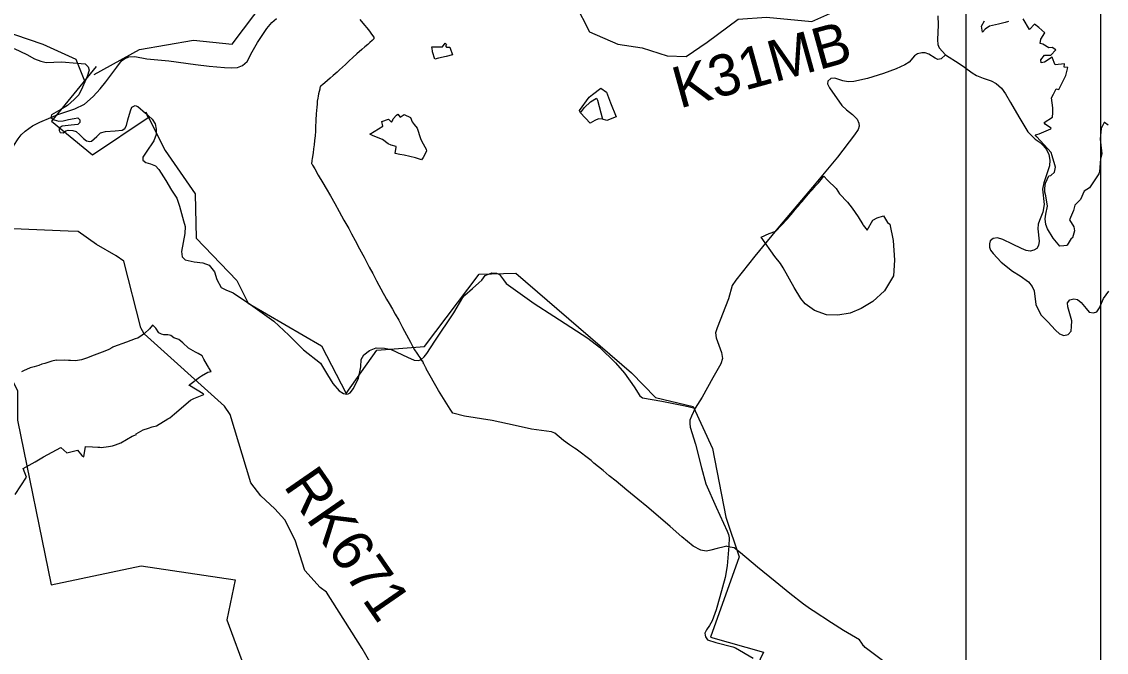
# Model space of a CAD drawing. Extents: x -789162 to -606354, y -1062736 to -945481.
# Drawn here: x -677802 to -673868, y -992822 to -990534 of the extents above; entities that cross this region are included whole.
import ezdxf

# ---------------------------------------------------------------- set-up
doc = ezdxf.new("R2010")
doc.units = 0
for name, color, linetype in [('_Rámeček', 7, 'Continuous'), ('_SIRSI VZTAHY_CYKLOTRASY MISTNI S', 7, 'Continuous'), ('_SIRSI VZTAHY_OP vodnich zdroju II stupne', 7, 'Continuous'), ('_SIRSI VZTAHY_SILNICE II TRIDY_STAV', 7, 'Continuous'), ('_SIRSI VZTAHY_SILNICE III TRIDY_STAV', 7, 'Continuous'), ('_SIRSI VZTAHY_USES_NRBC_S', 7, 'Continuous'), ('_SIRSI VZTAHY_USES_NRBK_S', 7, 'Continuous'), ('_SIRSI VZTAHY_USES_popis S', 7, 'Continuous'), ('_SIRSI VZTAHY_USES_RBK_S', 7, 'Continuous'), ('_SIRSI VZTAHY_VTL PLYNOVOD', 7, 'Continuous')]:
    doc.layers.add(name, color=color, linetype=linetype)

msp = doc.modelspace()

# ---------------------------------------------------------------- linework, layer by layer
at = {"layer": '_Rámeček'}
msp.add_lwpolyline([(-673887.2, -995977.3), (-673887.2, -966277.3), (-694887.2, -966277.3), (-694887.2, -995977.3)], close=True, dxfattribs=at)
msp.add_lwpolyline([(-674375.7, -995477.3), (-674375.7, -975976.1), (-694376.9, -975976.1), (-694376.9, -995477.3)], dxfattribs=at)
at = {"layer": '_SIRSI VZTAHY_CYKLOTRASY MISTNI S'}
for points in [[(-677538.3, -990724.9), (-677374.1, -990635), (-677178.3, -990600.9), (-677038.1, -990614.6), (-676918.4, -990457.2), (-676720, -990323.8), (-676593.5, -990299.8), (-676644.8, -990108.2), (-676566.2, -989978.1), (-676183.1, -989991.8), (-675933.5, -989844.7), (-675670.2, -989875.5), (-675396.6, -989998.7), (-675502.6, -989813.9), (-675834.3, -989697.5), (-675957.4, -989492.2)], [(-677573.3, -990749.2), (-677604, -990670.5), (-677724.4, -990616.5), (-678033.5, -990511.6)], [(-678766.8, -990700.2), (-678671.7, -990917.3), (-678371.7, -991161.7), (-678252.2, -991206.9), (-678082, -991285.8), (-678105.9, -991437.2), (-678023.6, -991453.2), (-677816.4, -991873), (-677816.4, -991979.3), (-677694.3, -992577.1), (-677369, -992507.8), (-677027.1, -992559.1), (-677057.4, -992704.3), (-676986, -992897.9), (-676961.7, -993127.6), (-676799.6, -993327.7), (-676711.2, -993548.4)], [(-677531.2, -990696.4), (-677694, -990894), (-677545.3, -991016.3), (-677343.5, -990880.7), (-677351.4, -990862.1), (-677281.6, -991001), (-677172.2, -991158.4), (-677168.8, -991319.2), (-677021, -991473), (-676980, -991555.1), (-676713.9, -991709.3), (-676625.4, -991882.5), (-676513.9, -991725.7), (-676341.2, -991712.7), (-676142.2, -991449.4), (-676009.5, -991445.8), (-675589.9, -991808.1), (-675502.6, -991897.5), (-675366.8, -991930.3), (-675295.6, -992081.9), (-675247.4, -992331.3), (-675199.6, -992475), (-675303.1, -992767.3), (-675110.9, -992821), (-675170.4, -992945.3)]]:
    msp.add_lwpolyline(points, dxfattribs=at)
at = {"layer": '_SIRSI VZTAHY_OP vodnich zdroju II stupne'}
for points in [[(-676312.2, -990639.3), (-676314.2, -990624.3), (-676275.9, -990624.2), (-676265.4, -990611.3), (-676261, -990615.8), (-676264.3, -990621.1), (-676261.4, -990626.2), (-676248.6, -990626), (-676247.4, -990629.9), (-676239.5, -990654), (-676262.7, -990659.4), (-676289.6, -990666.2), (-676303.5, -990669.4), (-676311.7, -990643.4)], [(-675775.3, -990864.8), (-675778.9, -990855.5), (-675744, -990807.8), (-675732, -990797.9), (-675700.6, -990774.6), (-675681.1, -990789.1), (-675665.6, -990827.8), (-675645.1, -990878.3), (-675679.1, -990891.7), (-675694.7, -990887.7), (-675709.1, -990886.6), (-675723.4, -990891.8), (-675740, -990901.9)], [(-675694.7, -990887.7), (-675709.1, -990886.6), (-675723.4, -990891.8), (-675740, -990901.9), (-675775.3, -990864.8), (-675759.9, -990844.6), (-675738.4, -990824.7), (-675716.7, -990811.3), (-675713.1, -990818)], [(-676334.6, -990995.8), (-676333.2, -991003.5), (-676346.1, -991025.9), (-676351.9, -991034.9), (-676373.2, -991027.6), (-676414.1, -991018.1), (-676429.8, -991014.9), (-676447.4, -991012.1), (-676443.6, -990989.1), (-676443.7, -990985.9), (-676462.1, -990981.9), (-676472.7, -990976.9), (-676493.5, -990961.6), (-676527.2, -990947.6), (-676539.6, -990941.2), (-676492.2, -990912.6), (-676495.1, -990895.2), (-676471.5, -990886.7), (-676460.5, -990897.8), (-676457.4, -990893.1), (-676454.6, -990886), (-676442.4, -990872.9), (-676438, -990869), (-676429.1, -990879.4), (-676425.5, -990877.5), (-676414.8, -990870.2), (-676391.6, -990881.6), (-676385, -990897.4), (-676378, -990906.1), (-676367.5, -990920.4), (-676355.2, -990957), (-676350.4, -990968.4)], [(-674892.5, -991093.6), (-674878.9, -991108), (-674847.3, -991139.3), (-674835.7, -991157.7), (-674806.2, -991188.8), (-674789.6, -991210.6), (-674767.3, -991241.2), (-674750.5, -991269.7), (-674749.4, -991271.7), (-674735.2, -991290.5), (-674714.6, -991254), (-674699.5, -991244.7), (-674676, -991238.2), (-674661.1, -991261.9), (-674652.6, -991268.7), (-674640.8, -991327.7), (-674635.5, -991398.5), (-674639.5, -991456), (-674672.6, -991509.7), (-674714.3, -991549.4), (-674757.3, -991573.8), (-674796.9, -991590.9), (-674841.9, -991598.8), (-674882.2, -991597.5), (-674925.8, -991581.7), (-674959.5, -991557.3), (-674975.8, -991537.6), (-674999.8, -991498.6), (-675040.2, -991427.2), (-675049.2, -991411.2), (-675070.2, -991385.1), (-675120.2, -991315.1), (-675090.1, -991302.6), (-675066.8, -991293.4), (-675025.6, -991250.7), (-675005.2, -991225.9), (-675000.6, -991220.5), (-674988.8, -991206.2), (-674984.7, -991202), (-674977.8, -991193.8), (-674972.7, -991187.6), (-674965.5, -991178.4), (-674961.1, -991173.9), (-674952.9, -991164.4), (-674948.6, -991159.9), (-674939.1, -991148.7), (-674935.5, -991144.5), (-674926.5, -991133.5), (-674922.5, -991128.8), (-674912.1, -991117.7)]]:
    msp.add_lwpolyline(points, close=True, dxfattribs=at)
msp.add_lwpolyline([(-677825, -992249.1), (-677784.1, -992185.8), (-677796.3, -992154.4), (-677752.7, -992130.3), (-677723, -992112.8), (-677660.3, -992079), (-677638.6, -992098.2), (-677599.6, -992088.1), (-677583.6, -992107.4), (-677576.1, -992112.1), (-677570.6, -992075), (-677545.4, -992076.1), (-677525.2, -992077.5), (-677521.1, -992077.5), (-677518.7, -992077.5), (-677513.4, -992078.9), (-677486.8, -992075.4), (-677472.4, -992073), (-677461.6, -992069.2), (-677441.8, -992061.1), (-677421.6, -992050.2), (-677401.3, -992037.4), (-677385.7, -992031.4), (-677386.4, -992028.9), (-677361.5, -992014.5), (-677341.3, -992008.4), (-677328.1, -992004.1), (-677313.1, -991999.9), (-677271.4, -991975.2), (-677264.8, -991971.3), (-677247, -991956.2), (-677189.7, -991906.6), (-677177.9, -991900.8), (-677141.2, -991886.4), (-677143, -991884.1), (-677193.1, -991853.6), (-677195.3, -991853.4), (-677192, -991850.4), (-677156.3, -991823.1), (-677153.1, -991820.6), (-677149.7, -991818.8), (-677126.4, -991805.7), (-677114, -991802.7), (-677122.6, -991789.9), (-677124.2, -991787.4), (-677127.9, -991781.6), (-677140.9, -991757.6), (-677147.2, -991746.4), (-677161.1, -991738.1), (-677171.1, -991732.2), (-677197.2, -991718.5), (-677217.7, -991699.2), (-677231.8, -991687.3), (-677249.4, -991680.2), (-677260.9, -991672.7), (-677265.2, -991670.6), (-677271.7, -991669.3), (-677286.2, -991669.3), (-677295.2, -991667.2), (-677303.9, -991663), (-677315.4, -991645.3), (-677327.2, -991633.6), (-677327.7, -991634.4), (-677338.3, -991648.4), (-677356, -991664.5), (-677364.9, -991671), (-677380.6, -991682.4), (-677390.5, -991684.1), (-677421.9, -991695.9), (-677468.6, -991712.8), (-677471.6, -991714.6), (-677474.7, -991716.4), (-677485.8, -991722.9), (-677500.4, -991728.9), (-677538.9, -991743.8), (-677566.6, -991754.6), (-677585.3, -991760), (-677606.3, -991763.9), (-677624.8, -991762.9), (-677632.2, -991762.6), (-677646.9, -991762.1), (-677676.2, -991763.2), (-677676.4, -991762.1), (-677692.7, -991765), (-677718.4, -991773.3), (-677729, -991776.8), (-677739.5, -991781), (-677756.6, -991785.9), (-677770.6, -991790), (-677794.8, -991800.6), (-677794.9, -991800.7), (-677802.6, -991804)], dxfattribs=at)
at = {"layer": '_SIRSI VZTAHY_SILNICE II TRIDY_STAV'}
for points in [[(-674478.7, -990512.8), (-674477.8, -990545.1), (-674480.2, -990599.4), (-674479, -990615.9), (-674473.7, -990628.8), (-674450.8, -990653.8), (-674450.8, -990654.3)], [(-677695.9, -990880.7), (-677670.3, -990870.2), (-677641.4, -990860.8), (-677609.2, -990849.9), (-677573.9, -990832.5), (-677543.1, -990805.1), (-677517.4, -990777.6), (-677496.4, -990751.8), (-677456.1, -990698.3), (-677439.6, -990676), (-677428.3, -990667.9), (-677412.8, -990661.4), (-677391.4, -990659.6), (-677348.1, -990668.3), (-677268.6, -990675), (-677171.5, -990689.2), (-677121.2, -990695), (-677065.7, -990699.5), (-677042.1, -990700.8), (-677019.5, -990699.2), (-677000.5, -990692.8), (-676984.4, -990677.5), (-676965.6, -990643.3), (-676946, -990609.2), (-676912.4, -990557.9), (-676894.7, -990535.9), (-676877.3, -990522.1)], [(-674450.8, -990654.3), (-674401.4, -990684.8), (-674382, -990699.1), (-674353.8, -990718.9), (-674338.5, -990729), (-674314.4, -990738.8), (-674285.4, -990748.3), (-674267.3, -990757.3), (-674248.5, -990774.2), (-674234, -990795.4), (-674215.2, -990826.9), (-674184.6, -990878.9), (-674153, -990932.6), (-674125.8, -990959.9), (-674108, -990972.1), (-674096.9, -990982.2), (-674085.3, -990997.1), (-674076.8, -991015), (-674072.3, -991035.6), (-674073.4, -991057), (-674094.6, -991118.4), (-674098.7, -991141.1), (-674093.1, -991196.3), (-674098.5, -991224.7), (-674110.4, -991254.4), (-674114.9, -991267.7), (-674116.2, -991285.6), (-674111.7, -991330.1), (-674113.8, -991345.7), (-674119.7, -991356.3), (-674130.3, -991362.6), (-674144.3, -991365.8), (-674158.6, -991363.4), (-674175.8, -991356.8), (-674208.6, -991341.1), (-674243.5, -991324.4), (-674262.6, -991317.5), (-674278.8, -991320.5), (-674289.6, -991329.3), (-674291.4, -991339.2), (-674291.1, -991351.5), (-674288.2, -991362.4), (-674278.2, -991374.3), (-674248.8, -991406), (-674208.6, -991438.4), (-674180.6, -991456.1), (-674150.4, -991477.7), (-674136.3, -991494.1), (-674129.5, -991510.1), (-674123.5, -991560.2), (-674112.7, -991583), (-674103.8, -991598.6), (-674079.5, -991622.2), (-674052.2, -991652.9), (-674038.2, -991666.4), (-674022.4, -991671.8), (-674006.3, -991668.5), (-673995.7, -991656.3), (-673993.5, -991639.6), (-673992.3, -991618.8), (-674007.8, -991568.7), (-674008.3, -991554.2), (-673999.6, -991543.1), (-673986.1, -991539.3), (-673972.8, -991541), (-673959.6, -991552.8), (-673940.3, -991574.5), (-673930.2, -991587), (-673914.2, -991590.4), (-673902.6, -991586.1), (-673892.1, -991571.8), (-673878.4, -991538.2), (-673858.8, -991511.7)], [(-678065.8, -991300.3), (-678040.2, -991270.2), (-677995, -991235.4), (-677961, -991206.7), (-677919.4, -991166.7), (-677895.8, -991133), (-677877.8, -991092.8), (-677847.5, -991021.9), (-677830.2, -990982.9), (-677814.9, -990958.6), (-677804.2, -990943.8), (-677789.1, -990930.2), (-677762.3, -990911.8), (-677735.5, -990898.3), (-677695.9, -990880.7)]]:
    msp.add_lwpolyline(points, dxfattribs=at)
at = {"layer": '_SIRSI VZTAHY_SILNICE III TRIDY_STAV'}
for points in [[(-677829.3, -990631), (-677783, -990652.5), (-677755.1, -990668.8), (-677732, -990677.1), (-677713.1, -990681.3), (-677657.5, -990679.7), (-677601.1, -990684.1), (-677571.1, -990686.4), (-677560.4, -990697), (-677557.3, -990709.1), (-677564.3, -990732.9), (-677581.1, -990770.7), (-677594.4, -990799.2), (-677611.6, -990816.4), (-677635.7, -990837.3), (-677660.1, -990852.6), (-677693.5, -990871.3), (-677695.9, -990880.7)], [(-674450.8, -990654.3), (-674466.7, -990668.3), (-674478.7, -990670.9), (-674488.9, -990665.8), (-674511.4, -990651.2), (-674525.2, -990647.1), (-674537.5, -990647.1), (-674552.7, -990650.6), (-674563.5, -990657.5), (-674583.2, -990680.4), (-674598.1, -990690.2), (-674630.6, -990705), (-674676, -990722), (-674733.7, -990739.8), (-674783.5, -990750.9), (-674803.8, -990752.2), (-674822.9, -990748), (-674852.7, -990737.9), (-674866.4, -990739.8), (-674877.5, -990749), (-674879.5, -990758.7), (-674872.4, -990773.4), (-674826.6, -990837.5), (-674810.3, -990853.8), (-674787.9, -990870.4), (-674771.5, -990887), (-674765.4, -990902.3), (-674764.8, -990912.2), (-674768.3, -990924.9), (-674781, -990944.6), (-674842.9, -991025.5), (-674933.2, -991133.7), (-675053.2, -991276.1), (-675142.8, -991384.6), (-675211.8, -991471), (-675224.5, -991490.7), (-675238.5, -991538.6), (-675279.3, -991644), (-675284.9, -991662.8), (-675282.9, -991681.2), (-675263.3, -991734.4), (-675260.2, -991756.1), (-675265.9, -991774.7), (-675294.7, -991825.7), (-675334.1, -991896.1), (-675359.3, -991935.8)], [(-677695.9, -990880.7), (-677683.4, -990889.7), (-677666.7, -990894.7), (-677651.7, -990893.5), (-677631.7, -990888.8), (-677611.9, -990884.4), (-677598.2, -990882.4), (-677590.6, -990889.1), (-677590.6, -990899.6), (-677597.7, -990906), (-677621.7, -990909), (-677654.7, -990912.6), (-677665.5, -990920.2), (-677665.9, -990928.1), (-677662, -990935.1), (-677651.8, -990937.2), (-677641.1, -990929.1), (-677632.8, -990927.1), (-677616, -990928.8), (-677604.4, -990932.4), (-677590.8, -990944.1), (-677577.9, -990956.8), (-677566.9, -990965.8), (-677554.3, -990968.3), (-677548.7, -990966.8), (-677529.7, -990949.9), (-677515.3, -990937.4), (-677498.3, -990931.7), (-677463, -990929.1), (-677437.9, -990927.5), (-677427.4, -990920.8), (-677421.4, -990909.7), (-677416.6, -990890), (-677407, -990856.5), (-677401.7, -990843.9), (-677389.8, -990837.7), (-677380, -990841.4), (-677352.4, -990866), (-677328.9, -990887.3), (-677318, -990903.6), (-677313.7, -990923.4), (-677314.4, -990942.4), (-677322.6, -990965.3), (-677350.3, -991006.6), (-677362.3, -991025.6), (-677362, -991036.4), (-677351.6, -991044.3), (-677334, -991049), (-677316.6, -991056.4), (-677304.1, -991069.7), (-677279.1, -991110.1), (-677258.1, -991145.1), (-677239.3, -991173.7), (-677229.2, -991202.9), (-677214.4, -991256.1), (-677208.7, -991276.7), (-677209.9, -991302.5), (-677222.6, -991367.9), (-677220.1, -991386.9), (-677208.5, -991397.6), (-677176.4, -991405.1), (-677144.5, -991408), (-677121.2, -991416.9), (-677102.6, -991440.6), (-677094.2, -991468.7), (-677077.9, -991498), (-677060.8, -991506.6), (-677035.1, -991517.7), (-676971.9, -991559.8), (-676886.7, -991620.3), (-676833, -991670.9), (-676779.3, -991724.6), (-676717.8, -991772.6), (-676692.5, -991815), (-676673.4, -991846), (-676650.1, -991872.8), (-676634.7, -991883.2), (-676623.9, -991885.5), (-676617.9, -991884), (-676610.5, -991880), (-676598, -991864.2), (-676580.4, -991827), (-676572.2, -991786.2), (-676570, -991759.8), (-676560.4, -991742.9), (-676540.7, -991727.2), (-676516.3, -991717.5), (-676485.6, -991718), (-676462.2, -991722.5), (-676402.7, -991750.9), (-676377.8, -991761.3), (-676360.9, -991762.9), (-676352.3, -991759.7), (-676341.7, -991750), (-676332.4, -991737.9), (-676303.1, -991692.4), (-676234.6, -991589.8), (-676201.2, -991534.1), (-676194.6, -991525.6), (-676166.1, -991502), (-676143.6, -991481.1), (-676133.1, -991471.4), (-676120.7, -991454.4), (-676096.4, -991445.2), (-676079.4, -991446.5), (-676068.2, -991450.8), (-676054.4, -991470.6), (-676044.3, -991483.4), (-676011.1, -991508.1), (-675942.5, -991556.1), (-675871.8, -991601.7), (-675748.5, -991682.5), (-675706.6, -991714.6), (-675647.5, -991771.4), (-675615.1, -991809.2), (-675580.5, -991858.7), (-675559.6, -991891.1), (-675549.7, -991898.4), (-675479.7, -991910), (-675395.4, -991927.3), (-675359.3, -991935.8)], [(-675359.3, -991935.8), (-675372.5, -991964.4), (-675377.9, -991979.3), (-675378.8, -991992), (-675377.6, -992005.3), (-675358.4, -992066.3), (-675336, -992152.3), (-675320.5, -992209.9), (-675283.4, -992295.1), (-675242.4, -992382.8), (-675238.2, -992394.3), (-675235.7, -992406.4), (-675237.2, -992435), (-675243.4, -992508), (-675250.4, -992550.5), (-675269.6, -992621), (-675283.3, -992667.7), (-675297.2, -992707.1), (-675307, -992724), (-675318.5, -992740.6), (-675323.6, -992752), (-675322.6, -992759.2), (-675321.7, -992765.1), (-675313.9, -992776.2), (-675283.6, -992786.1), (-675222.2, -992802.1), (-675212.5, -992806.1), (-675148.7, -992843.5)]]:
    msp.add_lwpolyline(points, dxfattribs=at)
at = {"layer": '_SIRSI VZTAHY_USES_NRBC_S'}
for points in [[(-674222.4, -990533.2), (-674234.1, -990536.7), (-674258.6, -990542.7), (-674292.1, -990549.7), (-674307.7, -990561), (-674316.6, -990571.4), (-674321, -990549.4), (-674309.8, -990530.7)], [(-673861, -990909), (-673875, -990899.7), (-673875.9, -990899.1), (-673876.2, -990899.6), (-673887, -990921), (-673890.1, -990960.4), (-673884, -991013.5), (-673889.1, -991031), (-673892.1, -991078.3), (-673894.9, -991086.1), (-673929.1, -991136.9), (-673948.1, -991148.9), (-673962, -991179.2), (-673982, -991198.8), (-673987, -991218.8), (-674001.5, -991252.1), (-673985.5, -991277.8), (-673983.8, -991293), (-673990.7, -991318.4), (-673995.3, -991319.8), (-674009.6, -991344.6), (-674011.9, -991345.5), (-674022.4, -991346.4), (-674036.6, -991347.6), (-674060.3, -991319.5), (-674081.7, -991285.5), (-674087.3, -991269.4), (-674089.2, -991249.2), (-674086.8, -991231.7), (-674080.8, -991202.4), (-674086.6, -991165.4), (-674090.6, -991151.6), (-674091.3, -991138.2), (-674088.7, -991118.9), (-674076.1, -991093), (-674068.8, -991091.9), (-674055.8, -991079.7), (-674052.1, -991061.6), (-674054.3, -991053), (-674064.6, -991019.7), (-674067.7, -991008.1), (-674119.7, -990950.9), (-674126, -990944.4), (-674111, -990940.8), (-674068.5, -990922), (-674067.3, -990919.4), (-674087.9, -990906.6), (-674093, -990899.2), (-674063.6, -990879.9), (-674062.2, -990864.2), (-674062.3, -990861), (-674062.3, -990850.8), (-674062.3, -990846.2), (-674066.4, -990809.7), (-674059.3, -990796.2), (-674049.3, -990777.3), (-674039.7, -990780.1), (-674014.8, -990728.3), (-674007.9, -990699.5), (-674020.1, -990698), (-674019.6, -990686.9), (-674053.6, -990689.7), (-674056.7, -990681.5), (-674064.1, -990662.4), (-674091.7, -990680.7), (-674103.6, -990682.9), (-674105.1, -990671.7), (-674091.8, -990654.7), (-674069.3, -990654.7), (-674050.4, -990635.5), (-674064.6, -990627.7), (-674076.9, -990628.7), (-674098.2, -990614.6), (-674108.2, -990613), (-674105.3, -990597.3), (-674091.4, -990573.7), (-674113, -990554.8), (-674128.4, -990542.7), (-674146.6, -990561.7), (-674169.3, -990523.5)]]:
    msp.add_lwpolyline(points, dxfattribs=at)
at = {"layer": '_SIRSI VZTAHY_USES_NRBK_S'}
msp.add_lwpolyline([(-677297.2, -989403.7), (-677181.7, -989672), (-677067.5, -989879.3), (-676942.7, -990041.4), (-676730.3, -990184.8), (-676573.7, -990224.7), (-676411.7, -990219.4), (-676286.9, -990168.9), (-675989.5, -990222), (-675888.6, -990261.9), (-675846.1, -990365.5), (-675742.6, -990570.1), (-675639, -990615.3), (-675551.4, -990628.6), (-675461.1, -990657.8), (-675392.1, -990660.4), (-675315.1, -990607.3), (-675203.6, -990524.9), (-675100, -990517), (-674935.4, -990532.9), (-674815.9, -990479.8), (-674752.2, -990389.4), (-674603.5, -990325.7), (-674403.8, -990311.3)], dxfattribs=at)
at = {"layer": '_SIRSI VZTAHY_USES_RBK_S'}
msp.add_lwpolyline([(-676480.8, -992957), (-676566.5, -992807.7), (-676695.8, -992603.5), (-676719.2, -992586.1), (-676774.7, -992525.4), (-676810.2, -992414.3), (-676847.5, -992341.5), (-676883.9, -992300.7), (-676934.2, -992253.8), (-676970.6, -992207), (-677045.2, -991958.8), (-677066, -991928.5), (-677357.3, -991665.6), (-677369.5, -991643.9), (-677431, -991402.7), (-677458.8, -991382.8), (-677529.9, -991342), (-677597.5, -991295.1), (-677633, -991293.4), (-677890.5, -991283)], dxfattribs=at)
at = {"layer": '_SIRSI VZTAHY_VTL PLYNOVOD'}
for points in [[(-676574.8, -990526.1), (-676564.2, -990538.5), (-676544.1, -990563.6), (-676529.1, -990583.7), (-676524.7, -990589.6), (-676524.4, -990591.5), (-676524.4, -990593.3), (-676524.9, -990595.4), (-676525.5, -990596.8), (-676530.7, -990601.8), (-676538.6, -990608.8), (-676546.6, -990616), (-676556.8, -990624.8), (-676567.9, -990634.3), (-676586.3, -990650), (-676600.5, -990663.1), (-676613.5, -990675.1), (-676618.2, -990679.4), (-676627.8, -990688.7), (-676638.1, -990698.6), (-676648.8, -990708.7), (-676658.1, -990717.1), (-676671.8, -990728.8), (-676683.2, -990738.8), (-676702.2, -990754.8), (-676710, -990761.1), (-676715.8, -990766.5), (-676717.4, -990768.1), (-676718.8, -990770.8), (-676719.8, -990773.9), (-676720.9, -990778.3), (-676723.2, -990787), (-676725.3, -990795.8), (-676726.8, -990803.8), (-676727.9, -990811), (-676729.5, -990822.1), (-676730.6, -990832.5), (-676731.5, -990843.2), (-676733.2, -990868), (-676734.9, -990890.8), (-676736, -990917.7), (-676736.6, -990930.4), (-676737.9, -990947.6), (-676739.8, -990964.8), (-676741.5, -990980.4), (-676743.3, -990994.9), (-676745, -991009.4), (-676747.8, -991030.5), (-676748.8, -991037.1), (-676749.1, -991039.7), (-676750, -991047.7), (-676749.4, -991049.9), (-676748.5, -991051.6), (-676746.7, -991054.5), (-676738.7, -991068), (-676726, -991090), (-676709.5, -991117.7), (-676697.2, -991139.1), (-676681.6, -991165.7), (-676665.7, -991193.1), (-676649.9, -991222.4), (-676633, -991253.5), (-676615.6, -991284.3), (-676605, -991303.7), (-676592.2, -991327.9), (-676576.5, -991357.2), (-676564.6, -991379.5), (-676559.7, -991388), (-676554.8, -991398.1), (-676548.5, -991410.1), (-676541.3, -991423.7), (-676528.7, -991447.6), (-676514.8, -991473.8), (-676506.1, -991490), (-676498.9, -991503.1), (-676490.1, -991519.1), (-676485.7, -991526.8), (-676478.2, -991539.8), (-676468.8, -991556.2), (-676457.1, -991576.3), (-676446.6, -991594.4), (-676434.4, -991616.7), (-676420.3, -991643), (-676405.8, -991670.2), (-676391.7, -991696.5), (-676384.4, -991710.4), (-676376.7, -991724.2), (-676368.8, -991736.6), (-676363.7, -991743.6), (-676362.8, -991744.9), (-676362, -991745.9), (-676361, -991747.5), (-676357.9, -991752.1), (-676354.3, -991757.5), (-676350, -991764.2), (-676349.7, -991764.6), (-676347.4, -991768), (-676345.9, -991770.7)], [(-676345.9, -991770.7), (-676346, -991770.8), (-676346.7, -991771.3), (-676346.5, -991771.8), (-676345.8, -991773), (-676345.1, -991772.5), (-676344.9, -991772.4)], [(-676345.9, -991770.7), (-676345.4, -991771.7), (-676344.9, -991772.4)], [(-674675, -992855.6), (-674742.8, -992804.6), (-674747.5, -992798.7), (-674748.1, -992797.9), (-674754.5, -992788.3), (-674763, -992777), (-674821.5, -992742.6), (-674865.1, -992715), (-674931.2, -992671.4), (-674940.4, -992665.2), (-674966.1, -992647.6), (-675015.7, -992608), (-675068.4, -992564.7), (-675133.1, -992512.6), (-675194.6, -992460.9), (-675217.3, -992443.2), (-675232.1, -992440.6), (-675242.6, -992437.6), (-675243.9, -992437.2), (-675254, -992438.6), (-675279.7, -992445.1), (-675301.8, -992450.7), (-675307, -992452.1), (-675319.6, -992454.3), (-675338.7, -992451.6), (-675366.7, -992436.8), (-675407.3, -992402.7), (-675449.6, -992365.2), (-675493.1, -992327.9), (-675533.8, -992293.1), (-675566.8, -992266), (-675607.1, -992233.1), (-675645.4, -992201.2), (-675671, -992180.9), (-675692.8, -992162.2), (-675726.3, -992135.7), (-675736.8, -992125.3), (-675791.1, -992084.7), (-675796.3, -992081.2), (-675814.3, -992068.8), (-675836.2, -992053.5), (-675868.1, -992027.1), (-675879.6, -992021.8), (-675952.7, -992011.7), (-676011.8, -991998.5), (-676095.6, -991980.9), (-676195.9, -991964.6), (-676237.9, -991954.3), (-676248.1, -991939.4), (-676289.4, -991871.4), (-676334.3, -991792.8), (-676335.1, -991791.2), (-676336, -991789.7), (-676343.4, -991775.1), (-676344.9, -991772.4)]]:
    msp.add_lwpolyline(points, dxfattribs=at)

# ---------------------------------------------------------------- texts
at = {"layer": '_SIRSI VZTAHY_USES_popis S'}
for s, rotation, p in [('K31MB', 15.4716, (-675415.5, -990849.1)), ('RK671', 304.6763, (-676854.8, -992217.9))]:
    msp.add_text(s, height=150, rotation=rotation, dxfattribs=at).set_placement(p)

doc.saveas('drawing.dxf')
